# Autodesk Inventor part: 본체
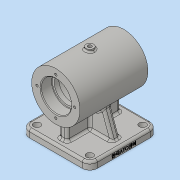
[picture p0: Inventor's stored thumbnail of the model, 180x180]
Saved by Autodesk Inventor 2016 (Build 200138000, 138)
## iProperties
Created: 2019-06
Part Number: 본체
Material: 일반
Document SubType Name: Modeling
Designer: Administrator
Density: 1 g/cm^3
Appearance: 기본값
Author: Administrator
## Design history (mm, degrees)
sketch "스케치1"
  geometry: L1 (-45, 45)-(45, 45); L2 (45, 45)-(45, -45); L3 (45, -45)-(-45, -45); L4 (-45, -45)-(-45, 45); L5 (-45, 45)-(45, -45); L6 (45, 45)-(-45, -45); 1 further point
  constraints: 12 end point, 2 midpoint, 2 parallel, 1 horizontal, 1 perpendicular
  dimensions: "d0" = 90 distance of L1.end L2.end; "d1" = 90 distance of L1.start L1.end
extrude "돌출1" new body sketch "스케치1" distance "d2" = 10; taper "d3" = 0 deg
sketch "스케치2"
  geometry: L1 (-45, 0)-(45, 0) reference; L2 (-45, 0)-(-45, 10) reference; L3 (45, 10)-(-45, 10) reference; L4 (45, 0)-(45, 10) reference; L5 (35, 10)-(14.982, 65); L6 (14.982, 65)-(-14.982, 65); L7 (-14.982, 65)-(-35, 10); L8 (35, 10)-(-35, 10); L9 (-45, 10)-(45, 10) reference; L10 (0, -9.469)-(0, 56.813) reference; 1 further point
  constraints: 8 end point, 2 point on line, 1 collinear, 1 horizontal, 1 symmetric about line
  dimensions: "d4" = 110 deg angle of L3 L7; "d5" = 110 deg angle of L3 L5; "d6" = 70 distance of L7.end L5.start; "d7" = 55 distance between parallel lines of L3 L6
extrude "돌출2" join sketch "스케치2" stored distance "d8" = 10; taper "d9" = 0 deg
sketch "스케치3"
  geometry: L1 (-45, 10)-(45, 10) reference; L2 (-35, 65)-(35, 65); L3 (35, 65)-(35, 10); L4 (35, 10)-(-35, 10); L5 (-35, 10)-(-35, 65); L6 (0, -13)-(0, 78) reference; 1 further point
  constraints: 8 end point, 2 parallel, 1 horizontal, 1 perpendicular, 1 point on line, 1 other
  dimensions: "d10" = 55 distance between parallel lines of L1 L2; "d11" = 70 distance between parallel lines of L5 L3
extrude "돌출3" join sketch "스케치3" stored distance "d12" = 10; taper "d13" = 0 deg
fillet "모깎기1" dims "d14" = 10
fillet "모깎기2" dims "d15" = 3
sketch "스케치4"
  geometry: L1 (-5, 65)-(5, 65) reference; C1 r 32 at (0, 65); 1 further point
  constraints: 1 centre point, 1 midpoint
  dimensions: "d16" = 64 diameter of C1
extrude "돌출4" join sketch "스케치4" stored distance "d17" = 90; taper "d18" = 0 deg
fillet "모깎기3" dims "d19" = 3
fillet "모깎기4" dims "d20" = 3
fillet "모깎기5" dims "d21" = 3
sketch "스케치5"
  geometry: L1 (45, 85)-(30, 85); L2 (30, 85)-(30, 82); L3 (30, 82)-(24, 82); L4 (24, 82)-(24, 90); L5 (24, 90)-(-24, 90); L6 (-24, 90)-(-24, 82); L7 (-24, 82)-(-30, 82); L8 (-30, 82)-(-30, 85); L9 (-30, 85)-(-45, 85); L10 (-45, 97)-(-45, 33) reference; L11 (45, 85)-(45, 65); L12 (45, 65)-(-45, 65); L13 (-45, 85)-(-45, 65); L14 (0, -19.4)-(0, 116.4) reference; 1 further point
  constraints: 24 end point, 6 perpendicular, 5 point on line, 1 collinear, 1 horizontal, 1 midpoint, 1 parallel
  dimensions: "d22" = 15 distance of L1.start L1.end; "d23" = 15 distance of L8.end L9.end; "d24" = 6 distance of L2.end L3.end; "d25" = 6 distance of L6.end L7.end; "d26" = 48 distance of L4.end L5.end; "d27" = 17 distance between parallel lines of L12 L7; "d28" = 25 distance between parallel lines of L12 L5; "d29" = 20 distance between parallel lines of L12 L1
revolve "회전1" sketch "스케치5" stored, may be unused: angle "d30" = 90 deg
chamfer "모따기1" distance "d31" = 1; stored, may be unused: second distance "d32" = 2, angle "d33" = 45 deg
chamfer "모따기2" distance "d34" = 1; stored, may be unused: second distance "d35" = 2, angle "d36" = 45 deg
fillet "모깎기6" dims "d37" = 0.6
fillet "모깎기7" dims "d38" = 3
node "작업 평면1"
sketch "스케치6"
  geometry: C1 r 5 at (0, 0); 1 further point
  constraints: 1 centre point, 1 coincident
  dimensions: "d39" = 10 diameter of C1
extrude "돌출5" join sketch "스케치6" stored distance "d40" = 6; taper "d41" = 0 deg
fillet "모깎기8" dims "d42" = 2
hole "구멍1" diameter "d45" = 4.917; stored, may be unused: countersink angle "d49" = 90 deg, drill point angle "d51" = 0 deg; dims "d43" = 10, "d44" = 10, "d46" = 12, "d47" = 4, "d48" = 2, "d50" = 17.1
sketch "스케치7"
  geometry: C1 r 32 at (0, 0) reference; 2 further points
  constraints: 1 vertical alignment
  dimensions: "d52" = 25 distance of C1.centre point (0, -25)
hole "구멍2" sketch "스케치7" at (0, -25) diameter "d53" = 3.242; stored, may be unused: countersink angle "d57" = 90 deg, drill point angle "d59" = 118 deg; dims "d54" = 7, "d55" = 4, "d56" = 2, "d58" = 9
sketch "스케치8"
  geometry: C1 r 1.621 at (0, 25) reference; 1 further point
hole "구멍3" sketch "스케치8" at (0, 25) diameter "d63" = 3.242; stored, may be unused: countersink angle "d67" = 90 deg, drill point angle "d69" = 118 deg; dims "d64" = 7, "d65" = 4, "d66" = 2, "d68" = 9
sketch "스케치9"
  geometry: L1 (-7, -10)-(0, -10) reference; 2 further points
  constraints: 1 other
  dimensions: "d73" = 4 distance of point (0, 35) point (-4, 35); "d74" = 45 distance from line of point (-4, 35) L1
feature "엠보싱1" sketch "스케치9" dims "d8" = 10, "d75" = 0.5, "d76" = 0
hole "구멍4" diameter "d79" = 9; stored, may be unused: countersink angle "d83" = 90 deg, drill point angle "d85" = 118 deg; dims "d77" = 10, "d78" = 10, "d80" = 7, "d81" = 4, "d82" = 2, "d84" = 10.8
hole "구멍5" diameter "d88" = 9; stored, may be unused: countersink angle "d92" = 90 deg, drill point angle "d94" = 118 deg; dims "d86" = 10, "d87" = 10, "d89" = 7, "d90" = 4, "d91" = 2, "d93" = 10.8
hole "구멍6" diameter "d97" = 9; stored, may be unused: countersink angle "d101" = 90 deg, drill point angle "d103" = 118 deg; dims "d95" = 10, "d96" = 10, "d98" = 7, "d99" = 4, "d100" = 2, "d102" = 10.8
hole "구멍7" diameter "d106" = 9; stored, may be unused: countersink angle "d110" = 90 deg, drill point angle "d112" = 118 deg; dims "d104" = 10, "d105" = 10, "d107" = 7, "d108" = 4, "d109" = 2, "d111" = 10.8
sketch "스케치10"
  geometry: L1 (-22.155, -40)-(22.155, -40); L2 (40, -22.155)-(40, 22.155); L3 (22.155, 40)-(-22.155, 40); L4 (-40, 22.155)-(-40, -22.155); L5 (-40, -40)-(40, 40); L6 (40, -40)-(-40, 40); L7 (63.1, 0)-(-63.6, 0) reference; L8 (0, -63)-(0, 63) reference; C1 r 4.5 at (-35, -35) reference; C2 r 4.5 at (35, -35) reference; C3 r 4.5 at (35, 35) reference; C4 r 4.5 at (-35, 35) reference; A1 r 10 centre (-35, -35) between (-25.119, -36.538) and (-36.538, -25.119); A2 r 10 centre (-35, 35) between (-36.538, 25.119) and (-25.119, 36.538); A3 r 10 centre (35, 35) between (25.119, 36.538) and (36.538, 25.119); A4 r 10 centre (35, -35) between (36.538, -25.119) and (25.119, -36.538); A5 r 3 centre (-37, -22.155) between (-40, -22.155) and (-36.538, -25.119); A6 r 3 centre (22.155, -37) between (22.155, -40) and (25.119, -36.538); A7 r 3 centre (-22.155, -37) between (-25.119, -36.538) and (-22.155, -40); A8 r 3 centre (37, -22.155) between (36.538, -25.119) and (40, -22.155); A9 r 3 centre (37, 22.155) between (40, 22.155) and (36.538, 25.119); A10 r 3 centre (22.155, 37) between (25.119, 36.538) and (22.155, 40); A11 r 3 centre (-22.155, 37) between (-22.155, 40) and (-25.119, 36.538); A12 r 3 centre (-37, 22.155) between (-36.538, 25.119) and (-40, 22.155); 9 further points
  constraints: 32 point on circle, 16 tangent, 12 centre point, 12 end point, 8 point on line, 7 equal radius, 4 coincident, 2 midpoint, 2 parallel, 1 horizontal, 1 perpendicular, 2 other
  dimensions: "d113" = 80 distance between parallel lines of L3 L1; "d114" = 80 distance between parallel lines of L2 L4; "d115" = 20 diameter of A4; "d116" = 20 diameter of A1; "d117" = 20 diameter of A2; "d118" = 20 diameter of A3; "d119" = 3 radius of A5
extrude "돌출6" cut sketch "스케치10" distance "d120" = 5; taper "d121" = 0 deg
feature "분할1"
node "솔리드1"
pattern_circular "원형 패턴1" dims angle "d61" = 360 deg
pattern_circular "원형 패턴2" dims angle "d71" = 360 deg
node "투영된 루프1"
